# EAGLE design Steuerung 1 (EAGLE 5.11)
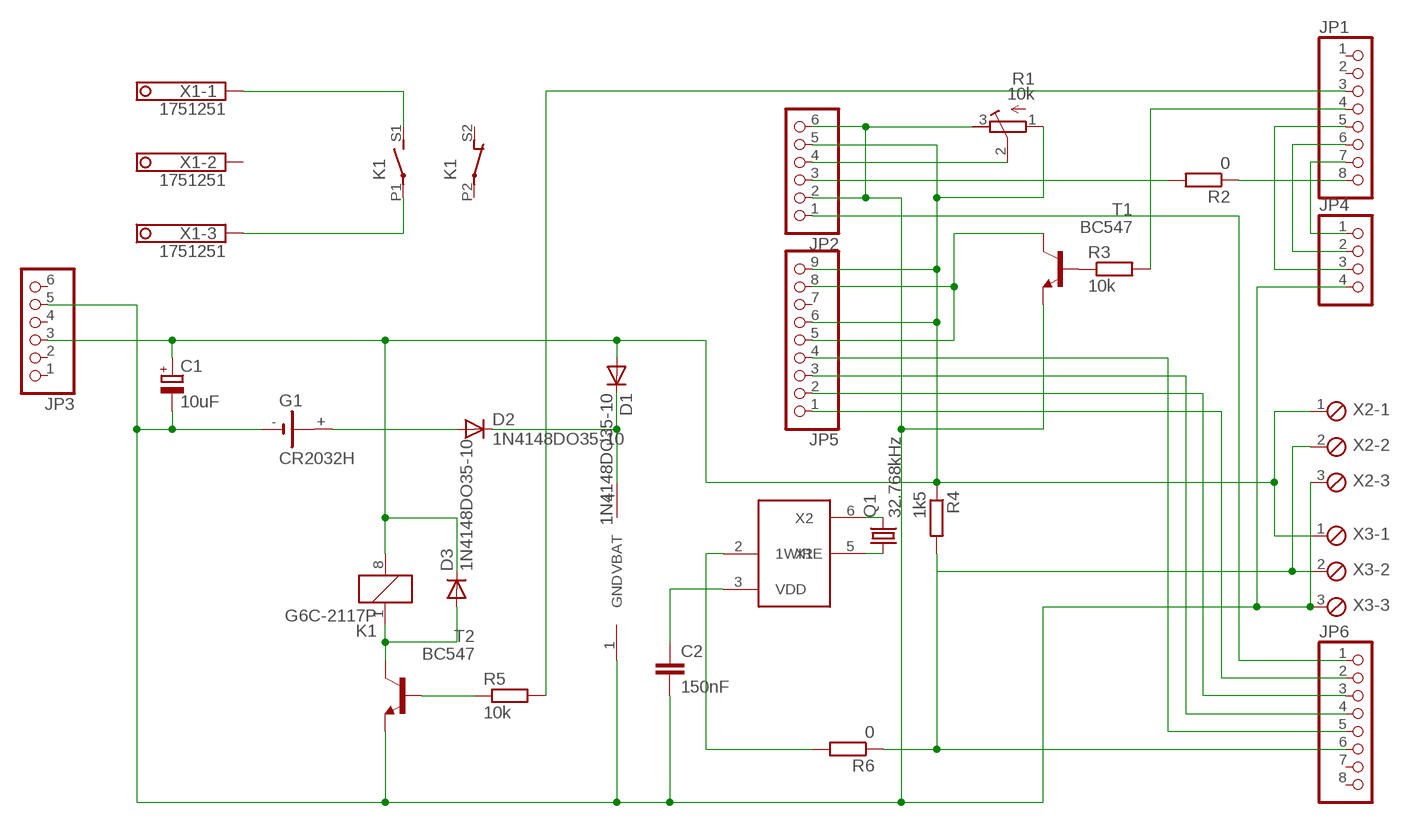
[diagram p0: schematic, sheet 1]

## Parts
C1  10uF  CPOL-EUE2,5-6E  [E2,5-6E]
C2  150nF  C-EU025-040X050  [C025-040X050]
D1  1N4148DO35-10  [DO35-10]
D2  1N4148DO35-10  [DO35-10]
D3  1N4148DO35-10  [DO35-10]
G1  CR2032H  [CR2032H]
JP1  PINHD-1X8  [1X08]
JP2  PINHD-1X6  [1X06]
JP3  PINHD-1X6  [1X06]
JP4  PINHD-1X4  [1X04]
JP5  PINHD-1X9  [1X09]
JP6  PINHD-1X8  [1X08]
K1  G6C-2117P  [G6C-2117P]
Q1  32.768kHz  CRYSTALTC38H  [TC38H]
R1  10k  R-TRIMM3339P  [RTRIM3339P]
R2  0  R-EU_0207/12  [0207/12]
R3  10k  R-EU_0207/12  [0207/12]
R4  1k5  R-EU_0207/12  [0207/12]
R5  10k  R-EU_0207/12  [0207/12]
R6  0  R-EU_0207/12  [0207/12]
T1  BC547  [TO92]
T2  BC547  [TO92]
U$1  DS2415  [TSOC6]
X1  1751251  [1751251]
X2  MPT3  [3POL254]
X3  MPT3  [3POL254]

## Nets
N$2: R3.1 T1.2(B)
N$3: K1.P1(2:P) X1.3
N$4: D2.A G1.+
N$5: C1.+ D1.A D3.C JP2.5 JP3.3 JP5.6 JP5.9 K1.8 R1.1(E) R4.1 X2.1 X3.1
N$6: Q1.2 U$1.6(X2)
N$7: Q1.1 U$1.5(X1)
N$8: JP5.4 JP6.5
N$9: JP5.3 JP6.4
N$10: JP5.2 JP6.3
N$11: JP5.1 JP6.2
N$12: JP2.1 JP6.1
N$13: JP1.3 R5.2
N$14: JP2.3 R2.2
N$15: JP2.4 R1.2(S)
N$16: D3.A K1.1 T2.3(C)
N$17: JP1.4 R3.2
N$18: JP5.5 JP5.8 T1.3(C)
N$19: R5.1 T2.2(B)
N$20: D1.C D2.C U$1.4(VBAT)
N$21: K1.S1(2:S) X1.1
N$22: C2.1 U$1.3(VDD)
N$23: JP1.7 JP4.1
N$24: JP1.6 JP4.2
N$26: JP1.5 JP4.3
N$28: R6.2 U$1.2(1WIRE)
N$29: C1.- C2.2 G1.- JP2.2 JP2.6 JP3.5 JP4.4 R1.3(A) T1.1(E) T2.1(E) U$1.1(GND) X2.3 X3.3
N$30: JP1.8 R2.1
N$32: JP6.6 R4.2 R6.1 X2.2 X3.2
Unconnected: G1.+@1(+) JP1.1 JP1.2 JP3.1 JP3.2 JP3.4 JP3.6 JP5.7 JP6.7 JP6.8 K1.P2(3:P) K1.S2(3:O) X1.2

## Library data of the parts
C1 = rcl:CPOL-EU: POLARIZED CAPACITOR, European symbol
C2 = resistor:C-EU: CAPACITOR, European symbol
D1-D3 = diode:1N4148: DIODE
G1 = battery:CR2032H: LI BATTERY Varta
JP1 JP6 = pinhead:PINHD-1X8: PIN HEADER
JP2 JP3 = pinhead:PINHD-1X6: PIN HEADER
JP4 = pinhead:PINHD-1X4: PIN HEADER
JP5 = pinhead:PINHD-1X9: PIN HEADER
K1 = relay:G6C-2117P: RELAY 1 x norm. open, 1x norm. closed, 10 A/240 V, Omron; OC_FARNELL: unknown; OC_NEWARK: unknown
Q1 = crystal:CRYSTAL: CRYSTAL; OC_FARNELL: unknown; OC_NEWARK: unknown
R1 = rcl:R-TRIMM: Trimm resistor
R2-R6 = resistor:R-EU_: RESISTOR, European symbol
T1 T2 = transistor:BC547: NPN TRANSISTOR
U$1 = 1wire:DS2415: One Wire Clock FEATURES  Real-time clock with fully compatible 1- Wire® MicroLAN interface  Uses the same binary time/date representation as the DS2404 but with 1 second resolution  Clock accuracy ±2 minutes per month at 25°C  Communicates at 16.3kbits per second  Unique, factory-lasered and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
X1 = con-phoenix-350:1751251: MKDS 1/ 3-3,5 Printklemme Nennstrom: 10 A Bemessungsspannung: 160 V Raster: 3,5 mm Polzahl: 3 Montageart: Löten Anschlussart: Schraubanschluss Anschlussrichtung vom Leiter zur Platine: 0° Source: http://eshop.phoenixcontact.com .. 1751251.pdf; OC_FARNELL: unknown; OC_NEWARK: unknown
X2 X3 = con-phoenix-254:MPT3: PHOENIX CONNECTOR; OC_FARNELL: unknown; OC_NEWARK: unknown

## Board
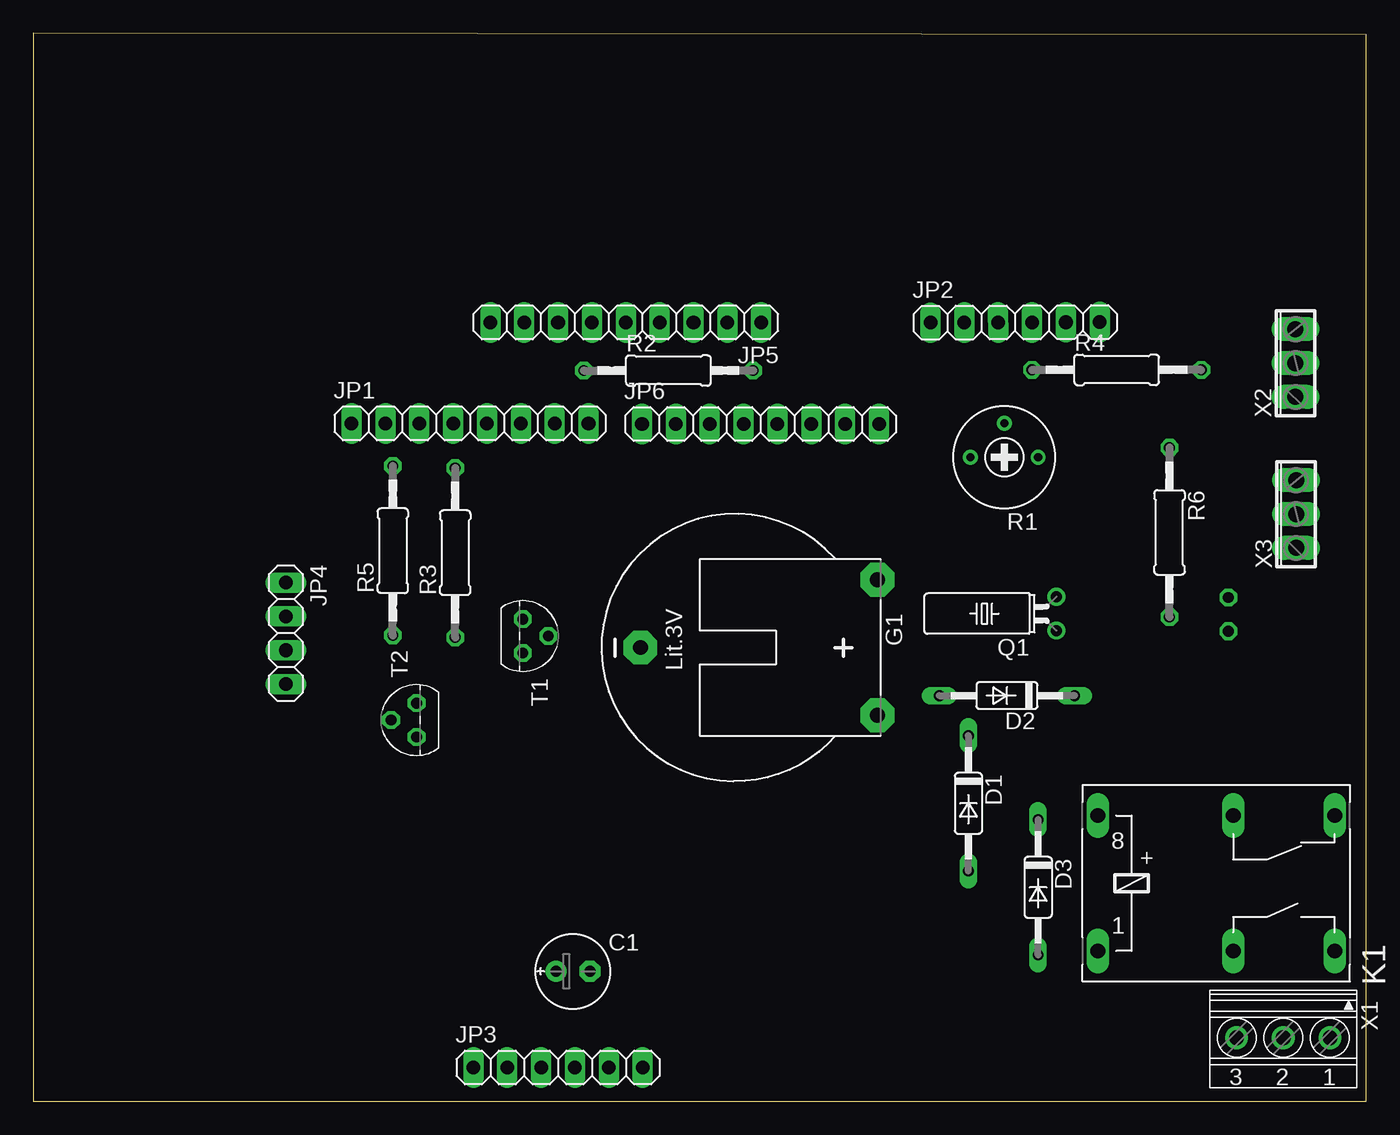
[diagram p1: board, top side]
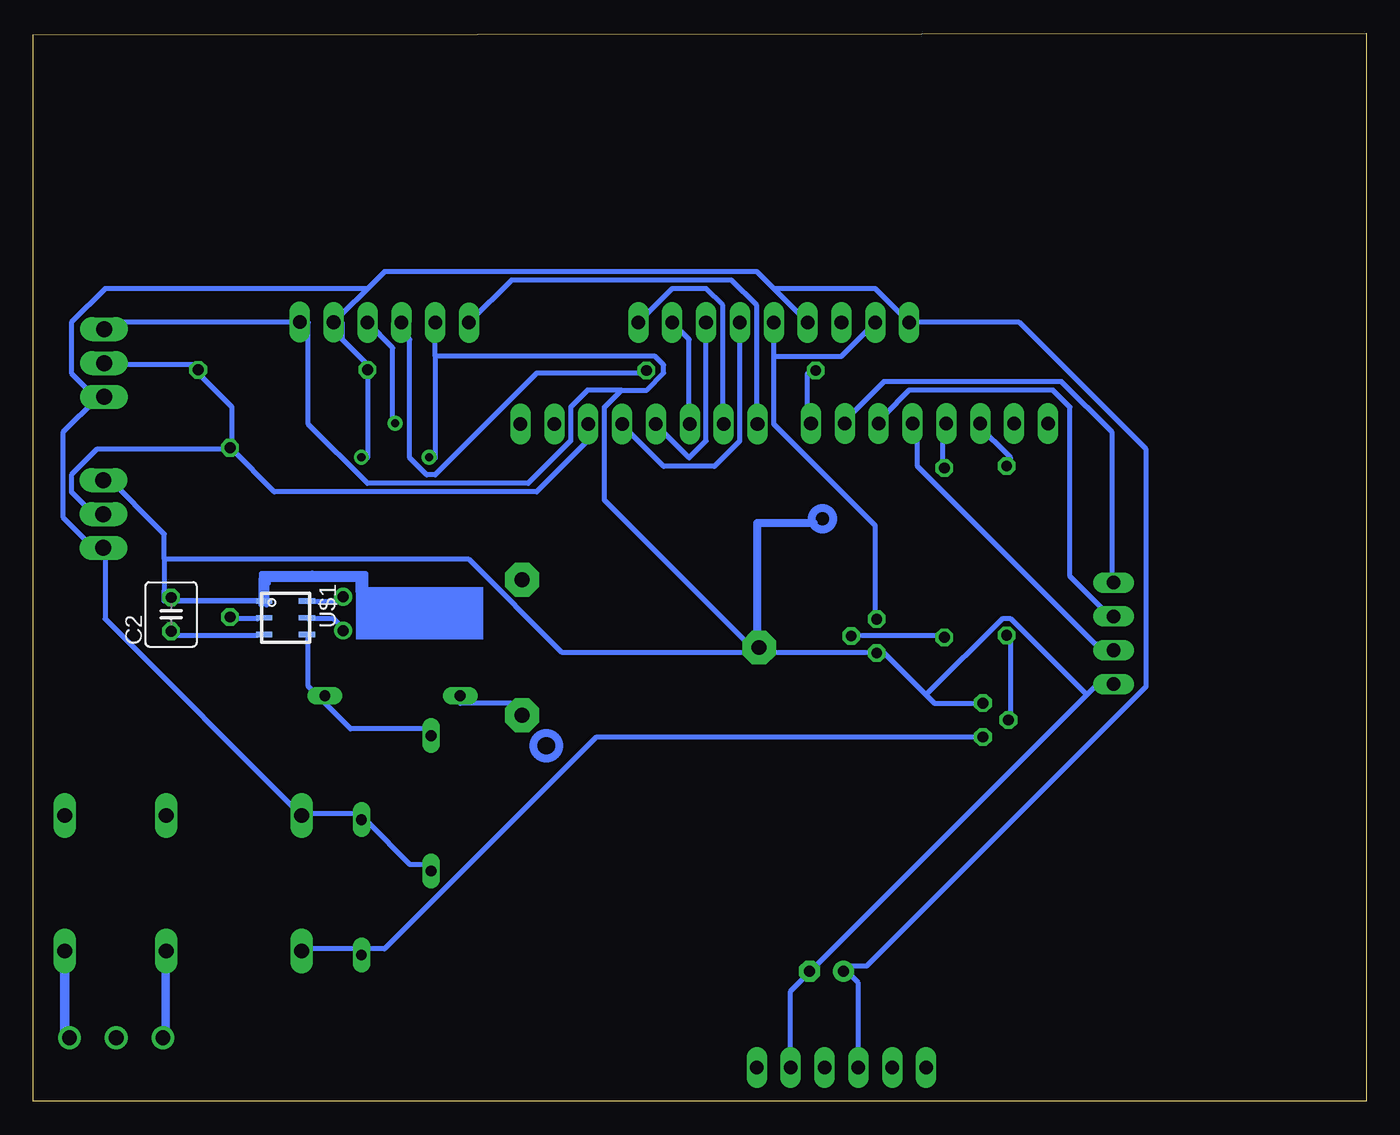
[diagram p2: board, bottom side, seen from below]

Size 100 x 80.1 mm. Coordinates in mm from the lower left corner, seen from the top.
Outline: 0,0 100,0 100,80 0,80.1 0,0
Copper layers (1*16): Top 0.035mm / dielectric 1.5mm / Bottom 0.035mm
Design rules "default *": minimum track width 15mil, minimum drill 24mil, track to track 8mil, track to pad 8mil, pad to pad 8mil, via to via 8mil, smd to smd 8mil, copper to edge 40mil, drill to drill 8mil, minimum pad ring 10mil, minimum via ring 8mil, stop-mask expansion 4mil, vias tented up to drill 0mil, thermal gap 10mil

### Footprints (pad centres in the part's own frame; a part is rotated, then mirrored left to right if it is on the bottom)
E2,5-6E = drill 0.813 pad 1.575 round: + -1.27,0 | drill 0.813 pad 1.575 octagon: - 1.27,0
C025-040X050 = drill 0.813 octagon: 1 -1.27,0; 2 1.27,0
DO35-10 = drill 0.813 long: A 5.08,0; C -5.08,0
CR2032H = drill 1.118 pad 2.54 octagon: + 5.08,10.795; +@1 -5.08,10.795; - 0,-6.985
1X08 = drill 1.016 long: 1 -8.89,0; 2 -6.35,0; 3 -3.81,0; 4 -1.27,0; 5 1.27,0; 6 3.81,0; 7 6.35,0; 8 8.89,0
1X06 = drill 1.016 long: 1 -6.35,0; 2 -3.81,0; 3 -1.27,0; 4 1.27,0; 5 3.81,0; 6 6.35,0
1X04 = drill 1.016 long: 1 -3.81,0; 2 -1.27,0; 3 1.27,0; 4 3.81,0
1X09 = drill 1.016 long: 1 -10.16,0; 2 -7.62,0; 3 -5.08,0; 4 -2.54,0; 5 0,0; 6 2.54,0; 7 5.08,0; 8 7.62,0; 9 10.16,0
G6C-2117P = drill 1.118 long: 1 -8.89,-5.08; 8 -8.89,5.08; P1 1.27,-5.08; P2 1.27,5.08; S1 8.89,-5.08; S2 8.89,5.08
TC38H = drill 0.813 round: 1 -1.27,0; 2 1.27,0
RTRIM3339P = drill 0.61 round: 1 -2.54,0; 2 0,-2.54; 3 2.54,0
0207/12 = drill 0.813 octagon: 1 -6.35,0; 2 6.35,0
TO92 = drill 0.813 octagon: 1 1.27,0; 2 0,1.905; 3 -1.27,0
TSOC6 = smd 0.406 x 1.219: 1 -1.27,-1.6; 2 0,-1.6; 3 1.27,-1.6; 4 1.27,1.6; 5 0,1.6; 6 -1.27,1.6
1751251 = drill 1.1 pad 1.7 round: 1 -3.5,-0.1; 2 0,-0.1; 3 3.5,-0.1
3POL254 = drill 1.2 long: 1 -2.54,0; 2 0,0; 3 2.54,0

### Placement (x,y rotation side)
C1  40.49,9.75 0 top
C2  89.66,36.53 90 bottom
D1  70.15,22.35 270 top
D2  73.05,30.43 180 top
D3  75.39,16.05 270 top
G1  52.53,34.04 270 top
JP1  32.77,50.85 0 top
JP2  73.66,58.42 0.2 top
JP3  39.37,2.54 0 top
JP4  18.95,35.1 270 top
JP5  44.45,58.42 180 top
JP6  54.56,50.8 0 top
K1  88.75,16.36 0 top
Q1  76.76,36.58 90 top
R1  72.85,48.31 180 top
R2  47.65,54.81 0 top
R3  31.65,41.15 90 top
R4  81.28,54.86 0 top
R5  26.97,41.3 90 top
R6  85.24,42.67 270 top
T1  36.73,34.9 270 top
T2  28.75,28.6 90 top
U$1  81.08,36.27 270 bottom
X1  93.78,4.67 180 top
X2  94.69,55.37 90 top
X3  94.74,44.04 90 top

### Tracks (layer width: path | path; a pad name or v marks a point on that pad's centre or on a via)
N$1
  Bottom 0.406: 82.4,38.86 82.5,38.86 82.5,37.34 | 75.34,39.32 75.44,39.32 75.44,38.25 75.64,38.25 75.64,39.17 | 75.64,39.17 75.29,39.17 | 76.15,39.17 82.75,39.17 | 82.75,39.17 82.86,39.17 | 82.86,39.17 82.86,39.27 81.89,39.27 | 75.29,38.46 75.08,38.46 75.08,39.57 76.15,39.57 | 76.15,39.57 79.05,39.57 | 79.05,39.57 79.1,39.57 | 79.1,39.57 79.1,39.62 | 81.89,39.27 79.05,39.27 79.05,39.57 | 79.1,39.57 82.86,39.57 82.86,39.47 81.89,39.47 81.89,39.27 | 76.15,39.17 75.64,39.17 | 76.15,39.57 76.15,39.17 | 82.5,37.34 82.75,37.34 82.75,39.17 | 82.86,39.17 82.91,39.17 82.91,37.24 | 82.5,37.34 82.5,37.24
N$2
  Bottom 0.381: R3.1 31.75,34.92 38.1,34.92 T1.2
N$3
  Bottom 0.381: K1.P1 90.17,10.79 90.17,5.08 X1.3
N$4
  Bottom 0.381: D2.A 67.94,29.84 64.14,29.84 63.5,29.21 G1.+
N$5
  Bottom 0.381: D1.A 70.48,17.78 71.75,17.78 74.93,20.95 D3.C 75.56,21.59 79.38,21.59 K1.8 94.61,36.2 94.61,41.27 X3.1 95.25,41.91 95.89,41.91 97.79,43.81 97.79,50.16 95.25,52.7 X2.1 95.25,53.34 95.89,53.34 97.16,54.61 97.16,58.42 94.61,60.96 74.93,60.96 | R1.1 74.93,48.26 R4.1 74.93,55.24 76.83,57.15 76.83,58.42 JP2.5 76.83,59.05 74.93,60.96 | 44.45,60.96 45.72,62.23 73.66,62.23 74.93,60.96 | 44.45,60.96 JP5.6 | JP3.3 38.1,8.89 38.73,9.53 C1.+ 38.73,10.16 37.47,10.16 16.51,31.11 16.51,48.9 26.04,58.42 JP5.9 36.83,60.96 44.45,60.96
N$6
  Bottom 0.381: U$1.6 79.38,37.47 76.83,37.47 Q1.2
N$7
  Bottom 0.381: U$1.5 79.38,36.2 77.47,36.2 76.83,35.56 Q1.1
N$8
  Bottom 0.381: JP5.4 46.99,49.53 48.9,47.62 52.7,47.62 55.88,50.8 JP6.5
N$9
  Bottom 0.381: JP5.3 49.53,49.53 50.8,48.26 52.7,50.16 52.7,50.8 JP6.4
N$10
  Bottom 0.381: JP5.2 50.8,57.15 50.8,50.8 JP6.3
N$11
  Bottom 0.381: JP5.1 52.07,60.96 49.53,60.96 48.26,59.69 48.26,50.8 JP6.2
N$12
  Bottom 0.381: JP6.1 45.72,50.8 45.72,59.69 47.62,61.59 64.14,61.59 67.31,58.42 JP2.1
N$13
  Bottom 0.381: R5.2 26.67,48.26 29.21,50.8 JP1.3
N$14
  Bottom 0.381: R2.2 54.61,54.61 62.23,54.61 69.85,46.99 70.48,46.99 71.75,48.26 71.75,57.15 72.39,57.78 JP2.3
N$15
  Bottom 0.381: R1.2 73.03,50.8 73.03,56.52 JP2.4
N$16
  Bottom 0.381: K1.1 79.38,11.43 75.56,11.43 D3.A 74.93,11.43 73.66,11.43 57.78,27.3 29.21,27.3 T2.3
N$17
  Bottom 0.381: R3.2 31.75,47.62 31.75,50.8 JP1.4
N$18
  Bottom 0.381: 44.45,55.88 JP5.5 | 44.45,55.88 44.45,50.8 36.83,43.18 36.83,36.2 T1.3 | JP5.8 39.37,55.88 44.45,55.88
N$19
  Bottom 0.381: T2.2 26.67,29.21 26.67,34.92 R5.1
N$20
  Bottom 0.381: U$1.4 79.38,34.92 79.38,31.11 78.74,30.48 D2.C 78.11,29.84 76.2,27.94 70.48,27.94 D1.C
N$21
  Bottom 0.381: K1.S1 97.79,10.79 97.79,5.08 X1.1
N$22
  Bottom 0.381: U$1.3 83.19,34.92 89.53,34.92 C2.1
N$23
  Bottom 0.381: JP4.1 19.05,39.37 19.05,50.16 22.86,53.98 36.2,53.98 38.73,51.44 JP1.7
N$24
  Bottom 0.381: JP4.2 19.05,36.83 19.68,36.83 22.23,39.37 22.23,52.07 23.5,53.34 34.29,53.34 36.2,51.44 JP1.6
N$26
  Bottom 0.381: JP4.3 19.05,34.29 20.32,34.29 33.66,47.62 33.66,50.8 JP1.5
N$28
  Bottom 0.381: U$1.2 83.19,36.2 85.09,36.2 R6.2
N$29
  Bottom 0.381: 20.95,30.48 41.27,10.16 C1.- 41.91,9.53 43.18,8.26 JP3.5 | 20.95,30.48 20.32,31.11 19.05,31.11 JP4.4 | 33.02,30.48 36.2,33.66 T1.1 36.83,33.66 45.09,33.66 G1.- 45.72,33.66 | 33.02,30.48 32.38,29.84 29.21,29.84 T2.1 | 20.95,30.48 26.67,36.2 27.3,36.2 33.02,30.48 | 69.85,55.88 69.85,48.26 R1.3 | 69.85,55.88 JP2.2 | 69.85,55.88 53.34,55.88 52.7,55.24 52.7,54.61 53.98,53.34 55.88,53.34 | 55.88,53.34 57.15,52.07 57.15,45.09 45.72,33.66 | 55.88,53.34 58.42,53.34 59.69,52.07 59.69,49.53 62.87,46.35 74.93,46.35 79.38,50.8 79.38,58.42 JP2.6 80.01,58.42 94.61,58.42 X2.3 | 90.17,40.64 90.17,42.55 94.61,46.99 X3.3 | 90.17,40.64 90.17,38.25 90.17,38.1 C2.2 | 45.72,33.66 60.33,33.66 67.31,40.64 90.17,40.64
  Bottom 0.406: U$1.1 90.17,37.54 90.17,38.25
N$30
  Bottom 0.381: R2.1 41.91,54.61 41.91,51.44 JP1.8
N$32
  Bottom 0.381: R6.1 85.09,49.53 85.09,52.07 87.63,54.61 R4.2 87.63,55.24 94.61,55.24 X2.2 | JP6.6 58.42,50.8 58.42,49.53 62.23,45.72 81.92,45.72 85.09,48.9 R6.1 | X3.2 95.25,44.45 95.89,44.45 97.16,45.72 97.16,46.99 95.25,48.9 85.72,48.9 R6.1
N$33
  Bottom 0.406: 89.81,11.28 89.97,11.28 89.97,4.37 90.37,4.37 90.37,4.62 90.68,4.62 90.68,4.78
N$34
  Bottom 0.61: 41.45,43.38 45.67,43.38 45.67,34.85
N$35
  Bottom 0.406: 97.64,11.43 97.48,11.43 97.48,4.22 97.33,4.22 97.33,4.78
(copper drawn outside any net)
  shapes: Bottom area x1, Bottom circle x2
